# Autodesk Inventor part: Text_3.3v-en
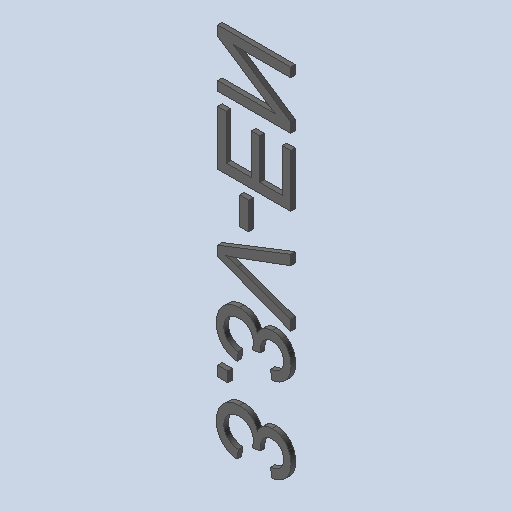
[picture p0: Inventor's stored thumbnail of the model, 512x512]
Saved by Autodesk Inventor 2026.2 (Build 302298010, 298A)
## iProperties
Created: 2026-10
Part Number: Text_3.3v-en
Material: Générique
Document SubType Name: Modeling
Designer: mel
Density: 1 g/cm^3
Appearance: Par défaut
Author: mel
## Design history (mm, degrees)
feature "Base1"
feature "Base2"
feature "Base3"
feature "Base4"
feature "Base5"
feature "Base6"
feature "Base7"
node "Solide1"
node "Solide2"
node "Solide3"
node "Solide4"
node "Solide5"
node "Solide6"
node "Solide7"
